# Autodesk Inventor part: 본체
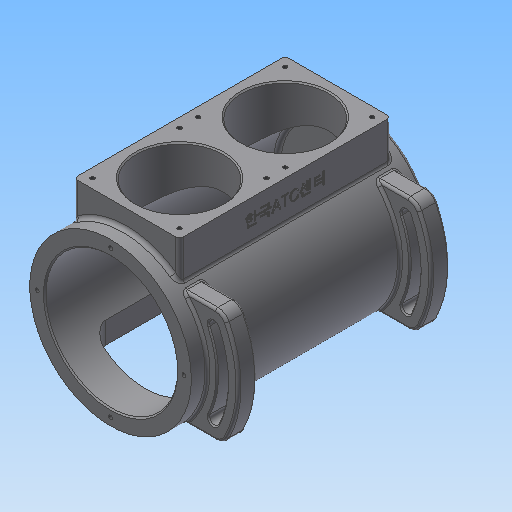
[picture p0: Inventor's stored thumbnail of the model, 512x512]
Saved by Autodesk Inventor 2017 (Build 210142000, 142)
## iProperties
Created: 2016-11
Part Number: 본체
Material: 알루미늄 6061
Document SubType Name: Modeling
Designer: mduedu
Density: 2.71 g/cm^3
Appearance: 기본값
Mass: 2446.31 g
Surface Area: 1767.27 cm^2
Volume: 902.698 cm^3
Author: mduedu
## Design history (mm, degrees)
sketch "스케치1"
  geometry: C1 r 65 at (0, 0); 1 further point
  constraints: 1 centre point, 1 coincident
  dimensions: "d119" = 130 diameter of C1
extrude "돌출1" new body sketch "스케치1" distance "d3" = 98; taper "d4" = 0 deg; dims "d132" = 97, "d133" = 0
feature "쉘1" dims "d120" = 12, "d134" = 8
node "작업 평면2"
sketch "스케치13"
  geometry: L1 (42.5, 85)-(-42.5, 85); L2 (-42.5, 85)-(-42.5, -85); L3 (-42.5, -85)-(42.5, -85); L4 (42.5, -85)-(42.5, 85); 2 further points
  constraints: 8 end point, 2 parallel, 1 horizontal, 1 midpoint, 1 perpendicular, 1 vertical alignment
  dimensions: "d122" = 170 distance of L1.end L2.end; "d124" = 85 distance of L2.end L3.end; "d125" = 85 distance from line of point (0, 0) L1 (= 0.5 x d122)
extrude "돌출11" join sketch "스케치13" stored distance "d126" = 10; taper "d127" = 0 deg
sketch "스케치14"
  geometry: L1 (65, 97)-(-65, 97) reference; C1 r 35 at (0, 42.5); 1 further point
  constraints: 1 centre point, 1 vertical alignment
  dimensions: "d128" = 70 diameter of C1; "d129" = 54.5 distance from line of C1.centre L1
extrude "돌출12" cut sketch "스케치14" stored distance "d130" = 10; taper "d131" = 0 deg
sketch "스케치15"
  geometry: C1 r 53 at (0, 0) reference; 1 further point
extrude "돌출13" cut sketch "스케치15" stored distance "d135" = 10; taper "d136" = 0 deg
chamfer "모따기1" distance "d54" = 1; stored, may be unused: second distance "d55" = 2, angle "d56" = 45 deg
sketch "스케치8"
  geometry: C1 r 30 at (0, 0); C2 r 65 at (0, 0) reference; 1 further point
  constraints: 1 centre point, 1 concentric
  dimensions: "d57" = 60 diameter of C1
extrude "돌출8" join sketch "스케치8" distance "d58" = 14; taper "d59" = 0 deg
hole "구멍3" diameter "d62" = 41; stored, may be unused: countersink angle "d66" = 90 deg, drill point angle "d68" = 0 deg; dims "d63" = 6, "d64" = 47, "d65" = 14, "d67" = 17, "d195" = 10, "d196" = 10
fillet "모깎기11" dims "d69" = 3
fillet "모깎기12" dims "d70" = 3
fillet "모깎기13" dims "d71" = 0.3
chamfer "모따기2" distance "d72" = 1; stored, may be unused: second distance "d73" = 2, angle "d74" = 45 deg
node "작업 평면3"
sketch "스케치16"
  geometry: L1 (-42.5, -80)-(47.5, -80); L2 (-42.5, -80)-(21.14, -16.36); L3 (-42.5, -80)-(21.14, -143.64); L4 (3.462, -34.038)-(34.879, -34.038); L5 (3.462, -125.962)-(34.879, -125.962); A1 r 65 centre (-42.5, -80) between (3.462, -34.038) and (3.462, -125.962) reference; A2 r 90 centre (-42.5, -80) between (34.879, -125.962) and (34.879, -34.038); A3 r 90 centre (-42.5, -80) between (34.879, -34.038) and (34.879, -125.962); A4 r 65 centre (-42.5, -80) between (3.462, -125.962) and (3.462, -34.038); 1 further point
  constraints: 11 point on circle, 10 end point, 3 centre point, 2 parallel, 2 point on line, 1 coincident, 1 horizontal
  dimensions: "d140" = 45 deg angle of L3 L1; "d141" = 45 deg angle of L2 L1; "d142" = 25 radial gap between concentric circles of A1 A2
extrude "돌출14" join sketch "스케치16" distance "d143" = 15; taper "d144" = 0 deg
sketch "스케치17"
  geometry: L1 (-42.5, -80)-(34.414, -80); L2 (-42.5, -80)-(27.208, -47.495); L3 (-42.5, -80)-(27.208, -112.505); L4 (34.879, -34.038)-(3.462, -34.038) reference; L5 (3.462, -125.962)-(34.879, -125.962) reference; A1 r 65 centre (-42.5, -80) between (3.462, -34.038) and (3.462, -125.962) reference; A2 r 76.914 centre (-42.5, -80) between (19.17, -125.962) and (19.17, -34.038); A3 r 4 centre (27.208, -47.495) between (23.582, -49.185) and (30.833, -45.804); A4 r 4 centre (27.208, -112.505) between (30.833, -114.196) and (23.582, -110.815); A5 r 80.914 centre (-42.5, -80) between (30.833, -114.196) and (30.833, -45.804); A6 r 72.914 centre (-42.5, -80) between (23.582, -110.815) and (23.582, -49.185); 1 further point
  constraints: 13 point on circle, 6 end point, 5 centre point, 5 coincident, 3 midpoint, 2 point on line, 1 equal radius, 1 horizontal
  dimensions: "d145" = 25 deg angle of L1 L3; "d146" = 25 deg angle of L2 L1; "d147" = 8 diameter of A3
extrude "돌출15" cut sketch "스케치17" stored distance "d150" = 15; taper "d151" = 0 deg
fillet "모깎기17" dims "d152" = 10
fillet "모깎기18" dims "d153" = 2
fillet "모깎기19" dims "d154" = 2
chamfer "모따기4" distance "d155" = 1; stored, may be unused: second distance "d156" = 2, angle "d157" = 45 deg
fillet "모깎기20" dims "d159" = 3
fillet "모깎기21" dims "d160" = 3
fillet "모깎기22" dims "d161" = 3
node "작업 평면4"
sketch "스케치18"
  geometry: L1 (-42.5, 70)-(42.5, 70); L2 (42.5, 70)-(42.5, -70); L3 (42.5, -70)-(-42.5, -70); L4 (-42.5, -70)-(-42.5, 70); 2 further points
  constraints: 8 end point, 2 parallel, 1 horizontal, 1 midpoint, 1 perpendicular, 1 vertical alignment
  dimensions: "d162" = 140 distance of L1.end L2.end; "d164" = 85 distance of L2.end L3.end; "d165" = 70 distance from line of point (0, 0) L1 (= 0.5 x d162)
extrude "돌출16" cut sketch "스케치18" stored distance "d166" = 15; taper "d167" = 0 deg
fillet "모깎기23" dims "d168" = 10
fillet "모깎기24" dims "d173" = 3
sketch "스케치19"
  geometry: 4 further points
  constraints: 4 other
hole "구멍6" sketch "스케치19" at (0, -59), (59, 0), (-59, 0), (0, 59) diameter "d174" = 3.242; stored, may be unused: countersink angle "d178" = 90 deg, drill point angle "d180" = 120 deg; dims "d175" = 8, "d176" = 4, "d177" = 2, "d179" = 10
sketch "스케치20"
  geometry: L1 (35, -77.5)-(-35, -77.5); L2 (-35, -77.5)-(-35, -7.5); L3 (-35, -7.5)-(35, -7.5); L4 (35, -7.5)-(35, -77.5); L5 (35, -77.5)-(-35, -7.5); L6 (-35, -77.5)-(35, -7.5); C1 r 36 at (0, -42.5) reference; 5 further points
  constraints: 12 end point, 4 coincident, 2 midpoint, 2 parallel, 1 horizontal, 1 perpendicular
  dimensions: "d181" = 70 distance of L2.end L3.end; "d182" = 70 distance of L1.end L2.end
hole "구멍7" sketch "스케치20" at (-35, -77.5), (-35, -7.5), (35, -7.5), (35, -77.5) diameter "d183" = 3.242; stored, may be unused: countersink angle "d187" = 90 deg, drill point angle "d189" = 118 deg; dims "d184" = 8, "d185" = 4, "d186" = 2, "d188" = 10
sketch "스케치21"
  geometry: L1 (164, 0)-(0, 0) reference; L2 (-3, 0)-(-3, -24.649) reference; 3 further points
  constraints: 1 midpoint, 1 vertical alignment, 1 other
  dimensions: "d190" = 15 distance from line of point (82, -15) L1; "d191" = 85 distance from line of point (82, 0) L2 (derived)
feature "엠보싱2" sketch "스케치21" dims "d3" = 98, "d4" = 0, "d119" = 130, "d132" = 97, "d133" = 0, "d192" = 0.5, "d193" = 0
node "솔리드1"
mirror "대칭5"
mirror "대칭6"
mirror "대칭7"
